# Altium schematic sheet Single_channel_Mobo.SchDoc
size A3
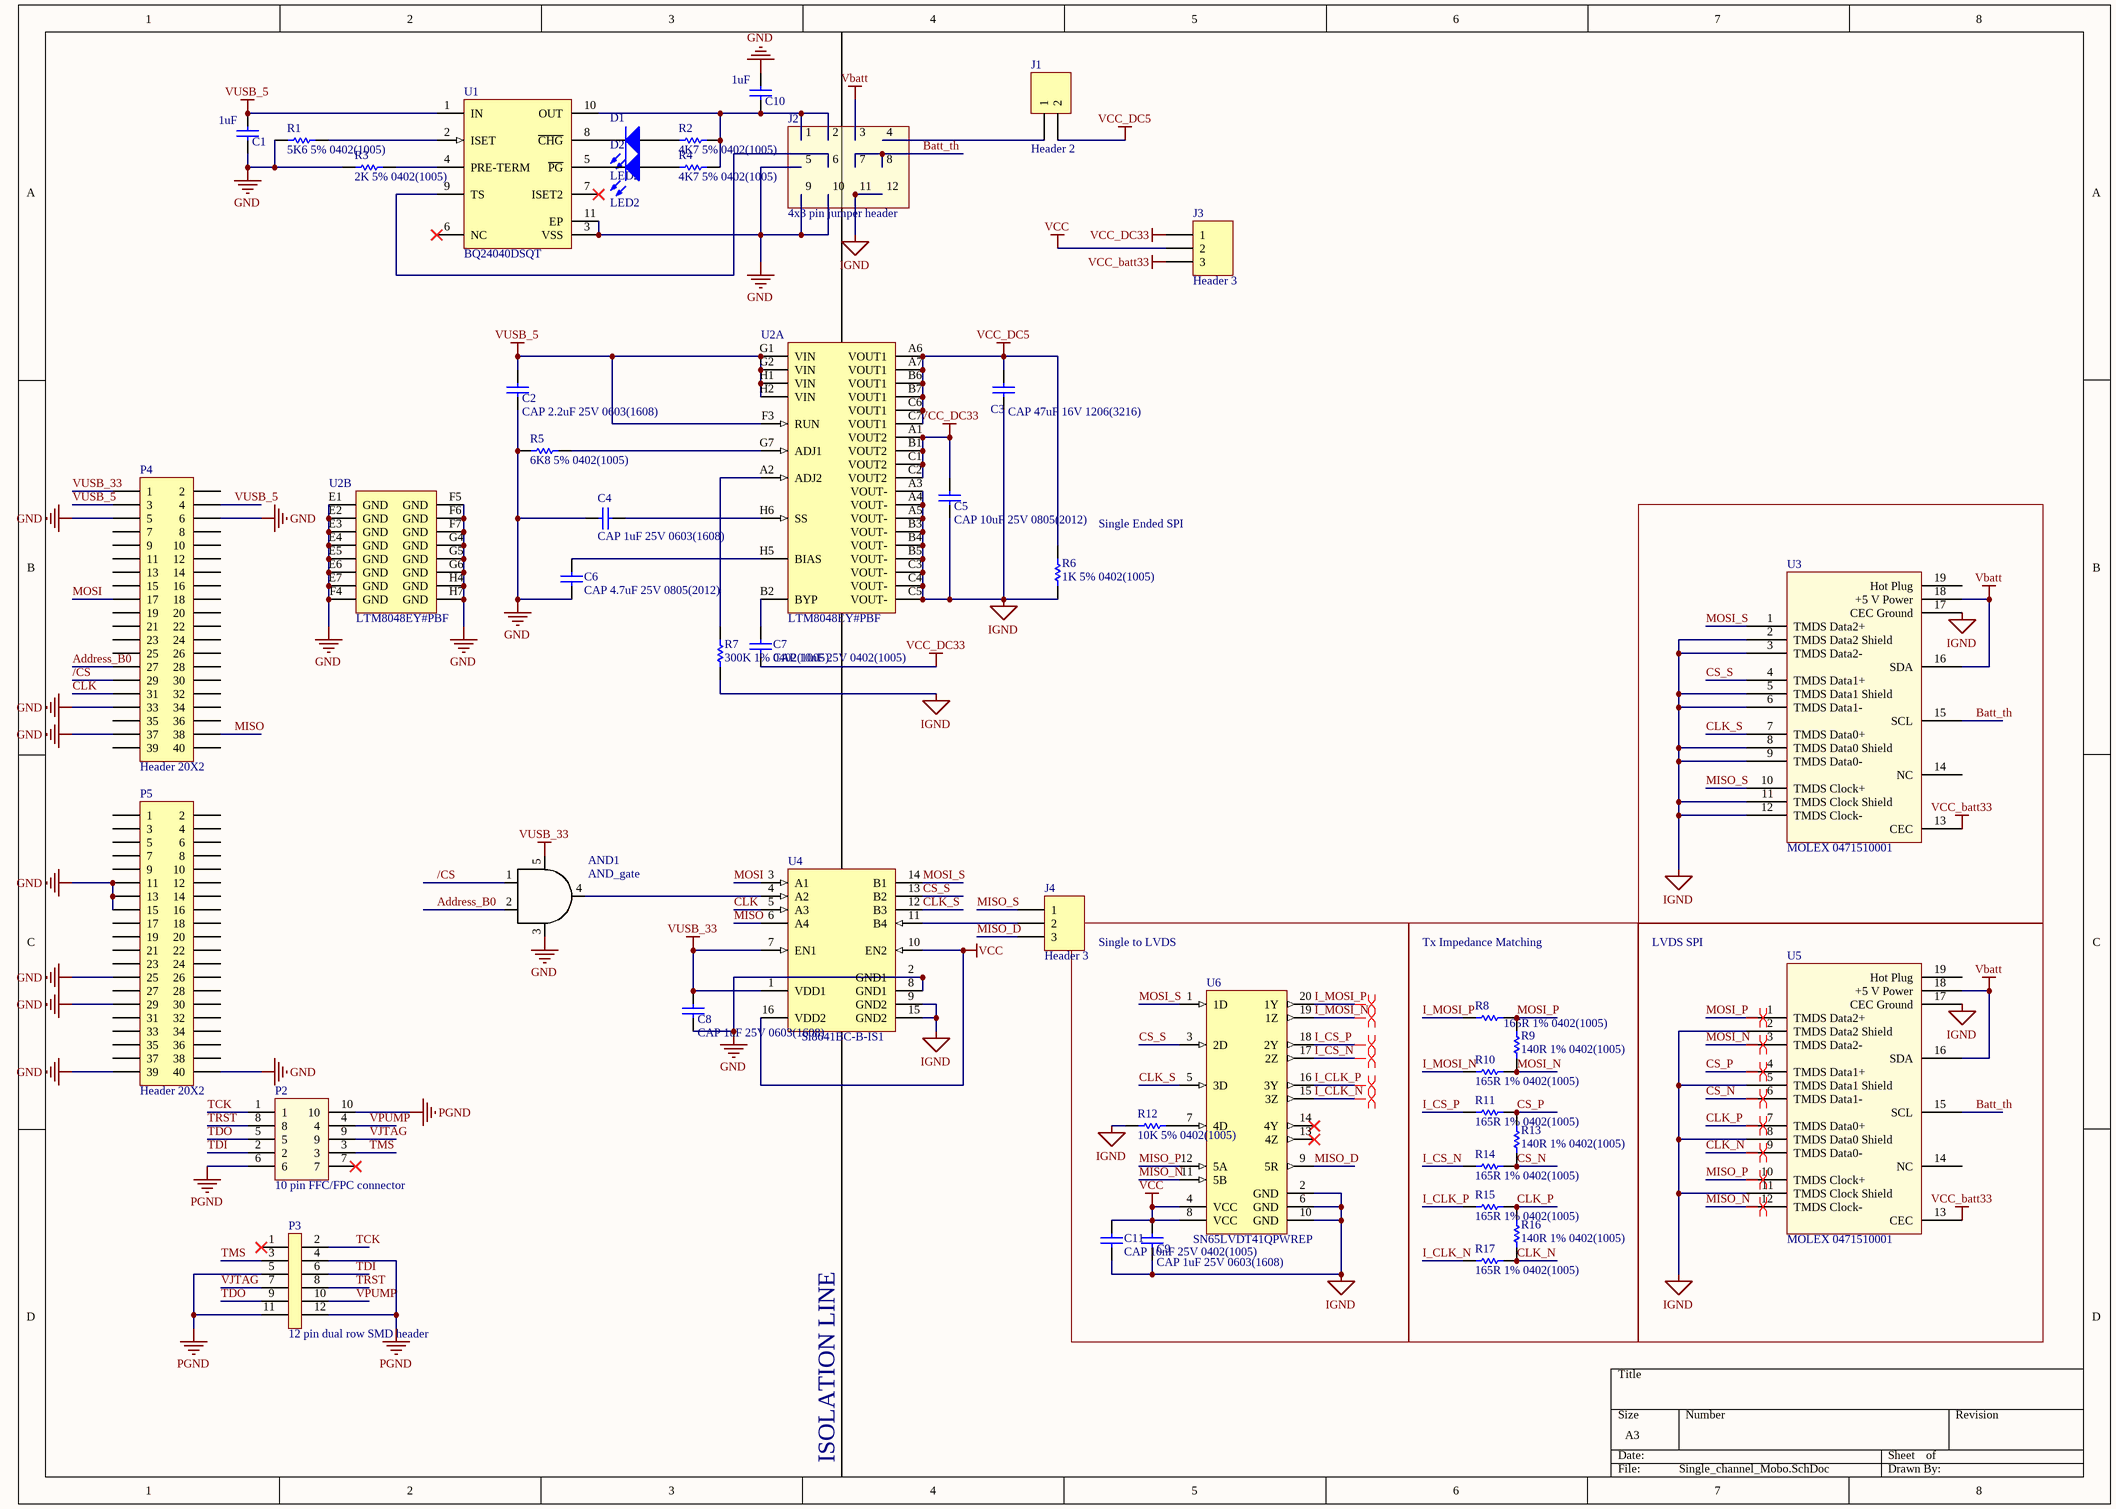
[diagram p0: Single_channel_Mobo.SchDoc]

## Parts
AND1  AND_gate  [TSOP5]
C1  value 1uF  [CAPC0603(1608)100_L]  (hidden comment: CAP 1uF 25V 0603(1608))
C2  CAP 2.2uF 25V 0603(1608)  [CAPC0603(1608)100_M]
C3  CAP 47uF 16V 1206(3216)  [CAPC1206(3216)190_M]
C4  CAP 1uF 25V 0603(1608)  [CAPC0603(1608)100_L]
C5  CAP 10uF 25V 0805(2012)  [CAPC0805(2012)145_N]
C6  CAP 4.7uF 25V 0805(2012)  [CAPC0805(2012)145_L]
C7  CAP 10nF 25V 0402(1005)  [CAPC0402(1005)60_L]
C8  CAP 1uF 25V 0603(1608)  [CAPC0603(1608)100_L]
C9  CAP 1uF 25V 0603(1608)  [CAPC0603(1608)100_L]
C10  value 1uF  [CAPC0603(1608)100_L]  (hidden comment: CAP 1uF 25V 0603(1608))
C11  CAP 10nF 25V 0402(1005)  [CAPC0402(1005)60_L]
D1  LED2  [LED 0610]
D2  LED2  [LED 0610]
J1  Header 2  [HDR1X2]
J2  4x3 pin jumper header  [4x3 pin jumper header]
J3  Header 3  [HDR1X3]
J4  Header 3  [HDR1X3]
P2  10 pin FFC/FPC connector  [10 FFC/FPC connector 0.5mm pitch]
P3  12 pin dual row SMD header  [TSM-106-01-S-DH]
P4  Header 20X2
P5  Header 20X2
R1  5K6 5% 0402(1005)  [RESC0402(1005)_L]
R2  4K7 5% 0402(1005)  [RESC0402(1005)_L]
R3  2K 5% 0402(1005)  [RESC0402(1005)_N]
R4  4K7 5% 0402(1005)  [RESC0402(1005)_L]
R5  6K8 5% 0402(1005)  [RESC0402(1005)_M]
R6  1K 5% 0402(1005)  [RESC0402(1005)_L]
R7  300K 1% 0402(1005)  [RESC0402(1005)_L]
R8  165R 1% 0402(1005)  [RESC0402(1005)_M]
R9  140R 1% 0402(1005)  [RESC0402(1005)_M]
R10  165R 1% 0402(1005)  [RESC0402(1005)_M]
R11  165R 1% 0402(1005)  [RESC0402(1005)_M]
R12  10K 5% 0402(1005)  [RESC0402(1005)_N]
R13  140R 1% 0402(1005)  [RESC0402(1005)_M]
R14  165R 1% 0402(1005)  [RESC0402(1005)_M]
R15  165R 1% 0402(1005)  [RESC0402(1005)_M]
R16  140R 1% 0402(1005)  [RESC0402(1005)_M]
R17  165R 1% 0402(1005)  [RESC0402(1005)_M]
U1  BQ24040DSQT  [DSQ10-1500X900TP]
U2  LTM8048EY#PBF  [LT-BGA-45-11250X9000X4920]  (parts A,B of 2)
U3  MOLEX 0471510001  [MOLEX 0471510001]
U4  Si8641BC-B-IS1  [SLAB-SOIC-16-NB_M]
U5  MOLEX 0471510001  [MOLEX 0471510001]
U6  SN65LVDT41QPWREP  [PW20_L]

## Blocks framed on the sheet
Single to LVDS: C9 C11 R12 U6
Tx Impedance Matching: R8-R11 R13-R17
LVDS SPI: U5

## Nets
GND: AND1.3(GND) C1.1 C2.1 C4.2 C6.2 C8.1 C10.2 J2.5 J2.9 J2.10 P4.5 P4.6 P4.33 P4.37 P5.11 P5.13 P5.15 P5.25 P5.29 P5.39 P5.40 R1.2 R3.2 R5.2 U1.3(VSS) U1.11(EP) U2.E1(GND) U2.E2(GND) U2.E3(GND) U2.E4(GND) U2.E5(GND) U2.E6(GND) U2.E7(GND) U2.F4(GND) U2.F5(GND) U2.F6(GND) U2.F7(GND) U2.G4(GND) U2.G5(GND) U2.G6(GND) U2.H4(GND) U2.H7(GND) U4.2(GND1) U4.8(GND1)
IGND: C3.1 C5.1 C9.1 C11.1 J2.11 J2.12 R6.1 R7.2 R12.1 U2.A3(VOUT-) U2.A4(VOUT-) U2.A5(VOUT-) U2.B3(VOUT-) U2.B4(VOUT-) U2.B5(VOUT-) U2.C3(VOUT-) U2.C4(VOUT-) U2.C5(VOUT-) U3.2(TMDS_Data2_Shield) U3.3(TMDS_Data2-) U3.5(TMDS_Data1_Shield) U3.6(TMDS_Data1-) U3.8(TMDS_Data0_Shield) U3.9(TMDS_Data0-) U3.11(TMDS_Clock_Shield) U3.12(TMDS_Clock-) U3.17(CEC_Ground) U4.9(GND2) U4.15(GND2) U5.2(TMDS_Data2_Shield) U5.5(TMDS_Data1_Shield) U5.8(TMDS_Data0_Shield) U5.11(TMDS_Clock_Shield) U5.17(CEC_Ground) U6.2(GND) U6.6(GND) U6.10(GND)
PGND: P2.6 P2.10 P3.4 P3.5 P3.11 P3.12
Vbatt: J2.3 U3.16(SDA) U3.18(+5_V_Power) U5.16(SDA) U5.18(+5_V_Power)
VCC: C9.2 C11.2 J3.2 U4.10(EN2) U4.16(VDD2) U6.4(VCC) U6.8(VCC)
VCC_batt33: J3.3 U3.13(CEC) U5.13(CEC)
VCC_DC5: C3.2 J1.2 R6.2 U2.A6(VOUT1) U2.A7(VOUT1) U2.B6(VOUT1) U2.B7(VOUT1) U2.C6(VOUT1) U2.C7(VOUT1)
VCC_DC33: C5.2 C7.1 J3.1 U2.A1(VOUT2) U2.B1(VOUT2) U2.C1(VOUT2) U2.C2(VOUT2)
VUSB_5: C1.2 C2.2 P4.3 P4.4 U1.1(IN) U2.F3(RUN) U2.G1(VIN) U2.G2(VIN) U2.H1(VIN) U2.H2(VIN)
VUSB_33: AND1.5(VCC) C8.2 P4.1 U4.1(VDD1) U4.7(EN1)
/CS: AND1.1(B) P4.29
Address_B0: AND1.2(A) P4.27
Batt_th: J2.7 J2.8 U3.15(SCL) U5.15(SCL)
CLK: P4.31 U4.5(A3)
CLK_N: R16.1 R17.1 U5.9(TMDS_Data0-)
CLK_P: R15.1 R16.2 U5.7(TMDS_Data0+)
CLK_S: U3.7(TMDS_Data0+) U4.12(B3) U6.5(3D)
CS_N: R13.1 R14.1 U5.6(TMDS_Data1-)
CS_P: R11.1 R13.2 U5.4(TMDS_Data1+)
CS_S: U3.4(TMDS_Data1+) U4.13(B2) U6.3(2D)
I_CLK_N: R17.2 U6.15(3Z)
I_CLK_P: R15.2 U6.16(3Y)
I_CS_N: R14.2 U6.17(2Z)
I_CS_P: R11.2 U6.18(2Y)
I_MOSI_N: R10.2 U6.19(1Z)
I_MOSI_P: R8.2 U6.20(1Y)
MISO: P4.38 U4.6(A4)
MISO_D: J4.3 U6.9(5R)
MISO_N: U5.12(TMDS_Clock-) U6.11(5B)
MISO_P: U5.10(TMDS_Clock+) U6.12(5A)
MISO_S: J4.1 U3.10(TMDS_Clock+)
MOSI: P4.17 U4.3(A1)
MOSI_N: R9.1 R10.1 U5.3(TMDS_Data2-)
MOSI_P: R8.1 R9.2 U5.1(TMDS_Data2+)
MOSI_S: U3.1(TMDS_Data2+) U4.14(B1) U6.1(1D)
TCK: P2.1 P3.2
TDI: P2.2 P3.6
TDO: P2.5 P3.9
TMS: P2.3 P3.3
TRST: P2.8 P3.8
VJTAG: P2.9 P3.7
VPUMP: P2.4 P3.10
NetAND1_4: AND1.4(Y) U4.4(A2)
NetC4_1: C4.1 U2.H6(SS)
NetC6_1: C6.1 U2.H5(BIAS)
NetC7_2: C7.2 U2.B2(BYP)
NetC10_1: C10.1 J2.1 J2.2 R2.2 R4.1 U1.10(OUT)
NetD1_1: D1.1(A) R2.1
NetD1_2: D1.2(K) U1.8(~{CHG})
NetD2_1: D2.1(A) R4.2
NetD2_2: D2.2(K) U1.5(~{PG})
NetJ1_1: J1.1 J2.4
NetJ2_6: J2.6 U1.9(TS)
NetJ4_2: J4.2 U4.11(B4)
NetR1_1: R1.1 U1.2(ISET)
NetR3_1: R3.1 U1.4(PRE-TERM)
NetR5_1: R5.1 U2.G7(ADJ1)
NetR7_1: R7.1 U2.A2(ADJ2)
NetR12_2: R12.2 U6.7(4D)

Not connected (* = marked no-connect by the designer): P2 7*; P3 1*; P4 2 7 8 9 10 11 12 13 14 15 16 18 19 20 21 22 23 24 25 26 28 30 32 34 35 36 39 40; P5 1 2 3 4 5 6 7 8 9 10 12 14 16 17 18 19 20 21 22 23 24 26 27 28 30 31 32 33 34 35 36 37 38; U1 6(NC)* 7(ISET2)*; U3 14(NC) 19(Hot_Plug); U5 14(NC) 19(Hot_Plug); U6 13(4Z)* 14(4Y)*

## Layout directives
differential pair: CLK_N, CLK_P, CS_N, CS_P, I_CLK_N, I_CLK_P, I_CS_N, I_CS_P, I_MOSI_N, I_MOSI_P, MISO_N, MISO_P, MOSI_N, MOSI_P

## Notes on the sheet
- (near R6) Single Ended SPI
- ISOLATION LINE

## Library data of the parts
C1 C4 C8-C10 = CMP-1035-02740-1: CAP 1uF 25V ±10% 0603 (1608 Metric) Thickness 1mm SMD; Case-Metric: 1608; Case-EIA: 0603
C2 = CMP-1035-02767-1: CAP 2.2uF 25V ±10% 0603 (1608 Metric) Thickness 1mm SMD; Case-Metric: 1608; Case-EIA: 0603
C3 = CMP-1037-05003-1: CAP 47uF 16V ±20% 1206 (3216 Metric) Thickness 1.9mm SMD; Case-Metric: 3216; Case-EIA: 1206
C5 = CMP-1036-04932-1: CAP 10uF 25V ±10% 0805 (2012 Metric) Thickness 1.45mm SMD; Case-Metric: 2012; Case-EIA: 0805
C6 = CMP-1036-04895-1: CAP 4.7uF 25V ±10% 0805 (2012 Metric) Thickness 1.45mm SMD; Case-Metric: 2012; Case-EIA: 0805
C7 C11 = CMP-1034-01879-1: CAP 10nF 25V ±5% 0402 (1005 Metric) Thickness 0.6mm SMD; Case-Metric: 1005; Case-EIA: 0402
D1 D2 = LED2: Typical RED, GREEN, YELLOW, AMBER GaAs LED
J1 = Header 2: Header, 2-Pin
J3 J4 = Header 3: Header, 3-Pin
P3 = 12 pin dual row SMD header: header
P4 P5 = Header 20X2: Header, 20-Pin, Dual row
R1 = CMP-1011-00092-1: 5K6 0.063W 5% 0402 (1005 Metric)  SMD; Case-Metric: 1005; Value: 5600.00 Ohm; Case-EIA: 0402
R2 R4 = CMP-1011-00090-1: 4K7 0.063W 5% 0402 (1005 Metric)  SMD; Value: 4700.00 Ohm; Case-Metric: 1005; Case-EIA: 0402
R3 = CMP-1011-00081-1: 2K 0.063W 5% 0402 (1005 Metric)  SMD; Case-Metric: 1005; Value: 2000.00 Ohm; Case-EIA: 0402
R5 = CMP-1011-00094-1: 6K8 0.063W 5% 0402 (1005 Metric)  SMD; Value: 6800.00 Ohm; Case-Metric: 1005; Case-EIA: 0402
R6 = CMP-1011-00074-1: 1K 0.063W 5% 0402 (1005 Metric)  SMD; Value: 1000.00 Ohm; Case-Metric: 1005; Case-EIA: 0402
R7 = CMP-1011-00788-1: 300K 0.063W 1% 0402 (1005 Metric)  SMD; Case-Metric: 1005; Value: 300000.00 Ohm; Case-EIA: 0402
R8 R10 R11 R14 R15 R17 = CMP-1011-00420-1: 165R 0.063W 1% 0402 (1005 Metric)  SMD; Case-Metric: 1005; Value: 165.00 Ohm; Case-EIA: 0402
R9 R13 R16 = CMP-1011-00412-1: 140R 0.063W 1% 0402 (1005 Metric)  SMD; Case-Metric: 1005; Value: 140.00 Ohm; Case-EIA: 0402
R12 = CMP-1011-00098-1: 10K 0.063W 5% 0402 (1005 Metric)  SMD; Case-Metric: 1005; Value: 10000.00 Ohm; Case-EIA: 0402
U1 = CMP-0321-00457-1: 800 mA, Single-Input, Single Cell Li-Ion Battery Charger with Auto Start. Vovp=6.6 V, 3.5 V, -40 to 85 degC, 10-pin SON (DSQ), Green (RoHS & no Sb/Br); Manufacturer: Texas Instruments; SubFamily: Battery Charge Management; Li-Ion: N; Vin(Min)(V): 3.5
U2 = CMP-0483-00034-1: 3.1 VIN to 32 VIN Isolated uModule DC/DC Converter with LDO Post Regulator, 45-pin BGA, -40 to 125 degC, Pb-Free, Tray; Manufacturer: Linear Technology; Extended Temp: E, I, MP; Ishutdown(uA): 1; Isupply(mA): 0.85; Number of Outputs: 2; Output Current(A): 0.44; Synchronous: no; Topology: Buck, LDO; Vin Max(V): 32; Vin Min(V): 3.1; Vout Max(V): 13; Vout Min(V): 1.2
U3 U5 = MOLEX 0471510001: MOLEX 0471510001 hdmi connector
U4 = CMP-0512-00190-1: Low-Power Quad-Channel Digital Isolator, 150 Mbps, 3.75 kVRMS Isolation Rating, -40 to 125 degC, 16-pin SOIC; Manufacturer: Silicon Labs; Maximum Data Rate (Mbps): 150; Maximum Propagation Delay (ns): 13; Sub-Family: Isolators; Enable Control: TRUE; Isolation Rating (kV): 3.75; Channel Type: Unidirectional; 10kV surge: FALSE
U6 = CMP-0327-00207-1: Enhanced Product Memorystick™ Interconnect Extender Chipset, -40 to +125 degC, 20-Pin TSSOP (PW), Green (RoHS & no Sb/Br); Manufacturer: Texas Instruments; SubFamily: LVDS PHY (<800Mbps)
